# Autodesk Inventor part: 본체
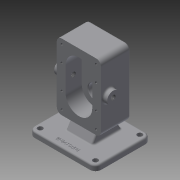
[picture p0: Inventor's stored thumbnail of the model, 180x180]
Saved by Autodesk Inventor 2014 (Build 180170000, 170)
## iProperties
Created: 2020-04
Part Number: 본체
Material: Generic
Document SubType Name: Modeling
Designer: kh
Density: 1 g/cm^3
Appearance: Default
Author: kh
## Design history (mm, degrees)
sketch "스케치1"
  geometry: L1 (-60, -50)-(60, -50); L2 (60, -50)-(60, 50); L3 (60, 50)-(-60, 50); L4 (-60, 50)-(-60, -50); L5 (-60, -50)-(60, 50); L6 (60, -50)-(-60, 50); 1 further point
  constraints: 12 end point, 2 midpoint, 2 parallel, 1 horizontal, 1 perpendicular
  dimensions: "d0" = 120 distance of L2.end L3.end; "d1" = 100 distance of L3.end L1.start
extrude "돌출1" new body sketch "스케치1" distance "d2" = 10; taper "d3" = 0 deg
node "작업 평면1"
sketch "스케치2"
  geometry: L1 (0, 0)-(120, 0) reference; L2 (120, 0)-(120, -10) reference; L3 (0, -10)-(120, -10) reference; L4 (0, 0)-(0, -10) reference; L5 (100, -150)-(20, -150); L6 (20, -150)-(20, -30); L7 (20, -30)-(100, -30); L8 (100, -30)-(100, -150); L9 (100, -90)-(20, -90); 3 further points
  constraints: 10 end point, 4 midpoint, 2 parallel, 1 horizontal, 1 perpendicular, 1 vertical alignment
  dimensions: "d5" = 90 distance between parallel lines of L9 L1; "d6" = 120 distance of L7.end L5.start; "d7" = 80 distance of L5.start L5.end
extrude "돌출2" join sketch "스케치2" distance "d8" = 53; taper "d9" = 0 deg
sketch "스케치3"
  geometry: L1 (100, -150)-(20, -150) reference; L2 (100, -30)-(100, -150) reference; L3 (20, -30)-(100, -30) reference; L4 (20, -150)-(20, -30) reference; L5 (120, 0)-(0, 0) reference; L6 (0, 0)-(0, -10) reference; L7 (120, -10)-(0, -10) reference; L8 (120, 0)-(120, -10) reference; L9 (100, -90)-(20, -90); C1 r 19 at (60, -112); 2 further points
  constraints: 3 midpoint, 2 end point, 1 centre point, 1 vertical alignment
  dimensions: "d10" = 22 distance from line of C1.centre L9; "d11" = 38 diameter of C1
extrude "돌출3" join sketch "스케치3" distance "d12" = 17; taper "d13" = 0 deg
sketch "스케치4"
  geometry: L1 (100, 150)-(20, 150) reference; L2 (20, 150)-(20, 30) reference; L3 (20, 30)-(100, 30) reference; L4 (100, 30)-(100, 150) reference; L5 (60, 112)-(60, 68); L6 (36, 112)-(36, 68); L7 (84, 68)-(84, 112); A1 r 24 centre (60, 112) between (84, 112) and (36, 112); A2 r 24 centre (60, 68) between (36, 68) and (84, 68); 4 further points
  constraints: 8 end point, 4 point on circle, 4 tangent, 3 midpoint, 2 centre point, 2 parallel, 1 horizontal alignment, 1 vertical alignment
  dimensions: "d14" = 92 dimension on A2 A1; "d16" = 22 distance of L5.start point (60, 90)
extrude "돌출4" cut sketch "스케치4" distance "d17" = 29; taper "d18" = 0 deg
sketch "스케치5"
  geometry: L1 (36, 68)-(36, 112) reference; L2 (84, 112)-(84, 68) reference; C1 r 19 at (60, 112) reference; C2 r 12.5 at (60, 112); C3 r 12.5 at (60, 68); A1 r 24 centre (60, 68) between (36, 68) and (84, 68) reference; A2 r 24 centre (60, 112) between (84, 112) and (36, 112) reference; 1 further point
  constraints: 2 centre point, 2 coincident, 1 equal radius
  dimensions: "d19" = 25 diameter of C2
extrude "돌출5" cut sketch "스케치5" distance "d20" = 15; taper "d21" = 0 deg
sketch "스케치6"
  geometry: C1 r 19 at (0, 0) reference; C2 r 14 at (0, 0); 1 further point
  constraints: 1 centre point, 1 coincident
  dimensions: "d22" = 28 diameter of C2
extrude "돌출6" cut sketch "스케치6" distance "d23" = 7.3; taper "d24" = 0 deg
sketch "스케치7"
  geometry: C1 r 14 at (0, 0) reference; C2 r 8.5 at (0, 0); 1 further point
  constraints: 1 centre point, 1 coincident
  dimensions: "d25" = 17 diameter of C2
extrude "돌출7" cut sketch "스케치7" stored distance "d26" = 7.3; taper "d27" = 0 deg
sketch "스케치8"
  geometry: L1 (120, 0)-(0, 0) reference; L2 (0, 0)-(0, -53) reference; L3 (120, -53)-(0, -53) reference; L4 (120, 0)-(120, -53) reference; L5 (150, -83)-(150, 17) reference; L6 (150, 17)-(140, 17) reference; L7 (140, -83)-(140, 17) reference; L8 (150, -83)-(140, -83) reference; C1 r 11 at (60, -39); 1 further point
  constraints: 1 centre point
  dimensions: "d28" = 22 diameter of C1; "d29" = 90 distance from line of C1.centre L5; "d30" = 14 distance from line of C1.centre L3
extrude "돌출8" join sketch "스케치8" distance "d31" = 8; taper "d32" = 0 deg
hole "구멍1" diameter "d35" = 8.376; stored, may be unused: countersink angle "d39" = 90 deg, drill point angle "d41" = 118 deg; dims "d36" = 6, "d37" = 4, "d38" = 2, "d40" = 8, "d82" = 10, "d83" = 10
sketch "스케치9"
  geometry: L1 (-44.03, -31.498)-(44.03, -31.498); L2 (44.03, -31.498)-(44.03, -48.502); L3 (44.03, -48.502)-(-44.03, -48.502); L4 (-44.03, -48.502)-(-44.03, -31.498); L5 (-44.03, -31.498)-(44.03, -48.502); L6 (44.03, -31.498)-(-44.03, -48.502); L7 (-60, 50)-(-60, -50) reference; L8 (-60, -50)-(60, -50) reference; 2 further points
  constraints: 4 end point, 1 midpoint, 2 other
  dimensions: "d42" = 60 distance from line of point (0, -40) L7; "d43" = 10 distance from line of point (0, -40) L8
feature "엠보싱1" sketch "스케치9" dims "d0" = 120, "d1" = 100, "d44" = 0.5, "d45" = 0
fillet "모깎기1" dims "d46" = 10
sketch "스케치10"
  geometry: L1 (-60, 40)-(-60, -40) reference; L2 (-50, -50)-(50, -50) reference; L3 (60, -40)-(60, 40) reference; L4 (50, 50)-(-50, 50) reference; L5 (15.014, -39.78)-(15.014, -41.089) reference; L6 (17.999, -40.885)-(18.046, -41.258) reference; L7 (14.566, -41.489)-(14.566, -37.86) reference; L8 (14.566, -37.86)-(17.463, -37.86) reference; L9 (17.463, -37.86)-(17.463, -38.233) reference; L10 (17.463, -38.233)-(15.014, -38.233) reference; L11 (15.014, -38.233)-(15.014, -39.406) reference; L12 (15.014, -39.406)-(17.198, -39.406) reference; L13 (17.198, -39.406)-(17.198, -39.78) reference; L14 (17.198, -39.78)-(15.014, -39.78) reference; L15 (12.449, -37.29)-(12.449, -41.666) reference; L16 (12.449, -41.666)-(11.995, -41.666) reference; L17 (11.995, -41.666)-(11.995, -37.079) reference; L18 (11.995, -37.079)-(12.354, -37.079) reference; L19 (11.289, -37.391)-(11.289, -41.415) reference; L20 (11.289, -41.415)-(10.834, -41.415) reference; L21 (10.834, -41.415)-(10.834, -38.993) reference; L22 (10.834, -38.993)-(9.803, -38.993) reference; L23 (9.803, -38.993)-(9.803, -38.647) reference; L24 (9.803, -38.647)-(10.834, -38.647) reference; L25 (10.834, -38.647)-(10.834, -37.154) reference; L26 (10.834, -37.154)-(11.208, -37.154) reference; L27 (12.592, -42.629)-(12.592, -43.002) reference; L28 (12.592, -43.002)-(8.27, -43.002) reference; L29 (8.27, -43.002)-(8.27, -41.089) reference; L30 (8.27, -41.089)-(8.602, -41.089) reference; L31 (8.718, -41.292)-(8.718, -42.629) reference; L32 (8.718, -42.629)-(12.592, -42.629) reference; L33 (10.414, -40.248)-(10.109, -40.594) reference; L34 (7.415, -40.797)-(7.103, -40.458) reference; L35 (8.67, -37.344)-(9.071, -37.344) reference; L36 (6.031, -40.98)-(6.479, -40.98) reference; L37 (6.438, -39.074)-(5.984, -39.074) reference; L38 (1.526, -37.615)-(1.526, -38.029) reference; L39 (1.526, -38.029)-(-0.034, -38.029) reference; L40 (-0.034, -38.029)-(-0.034, -42.615) reference; L41 (-0.034, -42.615)-(-0.488, -42.615) reference; L42 (-0.488, -42.615)-(-0.488, -38.029) reference; L43 (-0.488, -38.029)-(-2.042, -38.029) reference; L44 (-2.042, -38.029)-(-2.042, -37.615) reference; L45 (-2.042, -37.615)-(1.526, -37.615) reference; L46 (-10.095, -40.851)-(-8.284, -40.851) reference; L47 (-8.284, -40.851)-(-8.284, -42.975) reference; L48 (-8.284, -42.975)-(-8.745, -42.975) reference; L49 (-8.745, -42.975)-(-8.745, -41.225) reference; L50 (-8.745, -41.225)-(-12.578, -41.225) reference; L51 (-12.578, -41.225)-(-12.578, -40.851) reference; L52 (-12.578, -40.851)-(-10.55, -40.851) reference; L53 (-10.55, -40.851)-(-10.55, -39.63) reference; L54 (-10.55, -39.63)-(-13.311, -39.63) reference; L55 (-13.311, -39.63)-(-13.311, -39.257) reference; L56 (-13.311, -39.257)-(-8.942, -39.257) reference; L57 (-8.657, -37.588)-(-12.463, -37.588) reference; L58 (-12.463, -37.588)-(-12.463, -37.208) reference; L59 (-12.463, -37.208)-(-8.175, -37.208) reference; L60 (-8.446, -39.257)-(-7.307, -39.257) reference; L61 (-7.307, -39.257)-(-7.307, -39.63) reference; L62 (-7.307, -39.63)-(-10.095, -39.63) reference; L63 (-10.095, -39.63)-(-10.095, -40.851) reference; L64 (-2.917, -42.615)-(-3.474, -41.089) reference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; A1 r 10 centre (-50, 40) between (-50, 50) and (-60, 40) reference; A2 r 10 centre (-50, -40) between (-60, -40) and (-50, -50) reference; A3 r 10 centre (50, -40) between (50, -50) and (60, -40) reference; A4 r 10 centre (50, 40) between (60, 40) and (50, 50) reference; 58 further points
  constraints: 4 coincident, 68 other
hole "구멍2" sketch "스케치10" at (-50, 40), (-50, -40), (50, -40), (50, 40) diameter "d47" = 9; stored, may be unused: countersink angle "d51" = 90 deg, drill point angle "d53" = 118 deg; dims "d48" = 6, "d49" = 4, "d50" = 2, "d52" = 8
sketch "스케치11"
  geometry: L1 (36, 68)-(36, 112) reference; L2 (84, 112)-(84, 68) reference; L3 (100, 150)-(20, 150) reference; L4 (20, 150)-(20, 30) reference; L5 (20, 30)-(100, 30) reference; L6 (100, 30)-(100, 150) reference; L7 (20, 90)-(100, 90); L8 (60, 150)-(60, 30); L9 (29, 39)-(91, 39); L10 (91, 39)-(91, 141); L11 (91, 141)-(29, 141); L12 (29, 141)-(29, 39); L13 (29, 39)-(91, 141); L14 (91, 39)-(29, 141); L15 (29, 112)-(91, 112); L16 (29, 68)-(91, 68); A1 r 24 centre (60, 68) between (36, 68) and (84, 68) reference; A2 r 24 centre (60, 112) between (84, 112) and (36, 112) reference; 10 further points
  constraints: 20 end point, 8 coincident, 7 midpoint, 4 point on line, 3 parallel, 2 perpendicular, 1 horizontal
  dimensions: "d54" = 62 distance of L10.end L11.end; "d55" = 102 distance of L9.end L10.end; "d56" = 29 distance between parallel lines of L15 L11; "d57" = 44 distance between parallel lines of L16 L15
hole "구멍3" sketch "스케치11" at (29, 141), (29, 112), (29, 68), (29, 39), (91, 39), (91, 68), (91, 112), (91, 141) diameter "d58" = 4.134; stored, may be unused: countersink angle "d62" = 90 deg, drill point angle "d64" = 118 deg; dims "d59" = 10, "d60" = 4, "d61" = 2, "d63" = 12
fillet "모깎기2" dims "d65" = 9
sketch "스케치12"
  geometry: L1 (33, 30)-(-20, 30) reference; L2 (40, 10)-(-40, 10) reference; L3 (40, 10)-(50, 10) reference; L4 (50, 10)-(50, 0) reference; L5 (44.5, 0)-(35.5, 0) reference; L6 (50, 0)-(40, 0) reference; L7 (40, 0)-(-40, 0) reference; L8 (-35.5, 0)-(-44.5, 0) reference; L9 (-40, 0)-(-50, 0) reference; L10 (-50, 0)-(-50, 10) reference; L11 (-50, 10)-(-40, 10) reference; L12 (21.453, 30)-(33, 10); L13 (-8.453, 30)-(-20, 10); L14 (-20, 10)-(33, 10); L15 (-8.453, 30)-(21.453, 30); 1 further point
  constraints: 8 end point, 4 point on line, 1 collinear
  dimensions: "d66" = 17 horizontal distance of L12.end L4.end; "d67" = 60 deg angle of L2 L12; "d68" = 60 deg angle of L13 L2; "d69" = 53 distance of L13.end L12.end
extrude "돌출9" join sketch "스케치12" stored distance "d70" = 48; taper "d71" = 0 deg
chamfer "모따기1" distance "d72" = 0.7; stored, may be unused: second distance "d73" = 2, angle "d74" = 30 deg
fillet "모깎기3" dims "d75" = 0.5
chamfer "모따기2" distance "d76" = 1; stored, may be unused: second distance "d77" = 2, angle "d78" = 30 deg
fillet "모깎기4" dims "d79" = 3
fillet "모깎기5" dims "d80" = 3
fillet "모깎기6" dims "d81" = 3
node "솔리드1"
mirror "대칭1"
node "투영된 루프1"
node "투영된 루프2"
node "투영된 루프3"
node "투영된 루프4"
node "투영된 루프5"
node "투영된 루프6"
node "투영된 루프7"
node "투영된 루프8"
node "투영된 루프9"
node "투영된 루프10"
node "투영된 루프11"
other parameters: "d4" = -17
